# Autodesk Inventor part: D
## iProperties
Created: 2007-08
Part Number: D
Document SubType Name: Modeling
Designer: t-ikumi
Author: t-ikumi
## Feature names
1. 押し出し1 [Extrusion]
2. 押し出し2 [Extrusion]
3. フィレット1 [Fillet]
4. 押し出し3 [Extrusion]
5. 面取り1 [Chamfer]
6. 面取り2 [Chamfer]
